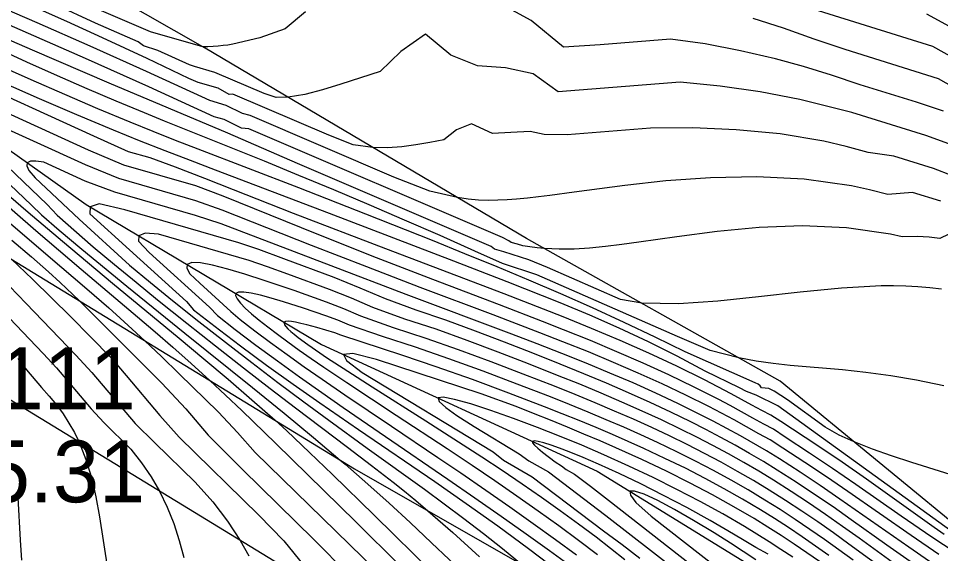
# Model space of a CAD drawing. Extents: x 2356077 to 2359823, y 225951 to 227822.
# Drawn here: x 2356810.76 to 2356847.97, y 227200.75 to 227222.36 of the extents above; entities that cross this region are included whole.
import ezdxf

# ---------------------------------------------------------------- set-up
doc = ezdxf.new("R2010")
doc.units = 0
for name, color, linetype in [('DTM Contours Major', 7, 'Continuous'), ('DTM Contours Minor', 7, 'Continuous'), ('Exist Roads EOP Cogo Elevation', 7, 'Continuous'), ('Exist Roads EOP Cogo Number', 7, 'Continuous'), ('PH Exist DTM Breakline', 7, 'Continuous')]:
    doc.layers.add(name, color=color, linetype=linetype)

msp = doc.modelspace()

# ---------------------------------------------------------------- linework, layer by layer
at = {"layer": 'DTM Contours Major'}
for points in [[(2356848.294, 227217.287), (2356847.369, 227217.623), (2356844.384, 227218.557), (2356842.283, 227219.085), (2356840.687, 227219.395), (2356839.073, 227219.622), (2356837.459, 227219.788), (2356832.543, 227219.386), (2356831.528, 227220.122), (2356830.407, 227220.355), (2356829.286, 227220.44), (2356828.21, 227220.876), (2356827.189, 227221.724), (2356826.195, 227221.017), (2356825.356, 227220.207), (2356823.771, 227219.702), (2356823.029, 227219.469), (2356822.318, 227219.283), (2356821.639, 227219.175), (2356821.162, 227219.162), (2356820.672, 227219.321), (2356818.687, 227220.172), (2356817.864, 227220.411), (2356817.666, 227220.483), (2356816.392, 227221.063), (2356815.81, 227221.256), (2356815.597, 227221.414), (2356813.867, 227222.16), (2356812.244, 227222.919)], [(2356848.104, 227207.527), (2356847.001, 227207.753), (2356845.953, 227207.929), (2356844.956, 227208.064), (2356844.004, 227208.166), (2356841.903, 227208.348), (2356841.218, 227208.424), (2356840.529, 227208.523), (2356839.83, 227208.656), (2356838.668, 227208.954), (2356837.346, 227209.514), (2356832.103, 227211.816), (2356831.671, 227212.001), (2356830.292, 227212.458), (2356829.182, 227212.961), (2356827.771, 227213.589), (2356826.345, 227214.213), (2356824.913, 227214.829), (2356823.486, 227215.433), (2356822.074, 227216.02), (2356820.688, 227216.587), (2356816.656, 227218.208), (2356815.848, 227218.54), (2356814.703, 227219.019), (2356813.535, 227219.518), (2356812.338, 227220.041), (2356811.106, 227220.589), (2356809.833, 227221.165)], [(2356847.899, 227200.71), (2356846.777, 227201.476), (2356844.221, 227203.26), (2356843.357, 227203.852), (2356842.486, 227204.431), (2356841.6, 227205.003), (2356841.095, 227205.337), (2356840.632, 227205.581), (2356840.137, 227205.866), (2356839.637, 227206.145), (2356839.13, 227206.418), (2356838.615, 227206.687), (2356837.69, 227207.148), (2356836.739, 227207.599), (2356835.764, 227208.038), (2356834.769, 227208.469), (2356833.755, 227208.89), (2356832.726, 227209.304), (2356831.799, 227209.667), (2356829.909, 227210.388), (2356826.966, 227211.498), (2356824.821, 227212.322), (2356822.59, 227213.194), (2356818.983, 227214.621), (2356817.924, 227214.995), (2356814.814, 227215.896), (2356813.462, 227216.44), (2356809.255, 227218.357)], [(2356809.031, 227217.596), (2356811.917, 227214.85), (2356812.332, 227214.413), (2356813.779, 227213.138), (2356814.638, 227212.422), (2356815.506, 227211.708), (2356816.375, 227211), (2356817.556, 227210.052), (2356818.714, 227209.135), (2356819.837, 227208.255), (2356820.915, 227207.421), (2356821.938, 227206.637), (2356824.036, 227205.052), (2356825.012, 227204.312), (2356825.885, 227203.632), (2356826.332, 227203.272), (2356826.794, 227202.891), (2356827.277, 227202.483), (2356828.283, 227201.603), (2356829.367, 227200.622)], [(2356810.496, 227213.404), (2356811.288, 227212.729), (2356811.972, 227212.127), (2356812.445, 227211.695), (2356812.953, 227211.216), (2356813.229, 227210.95), (2356813.932, 227210.26), (2356814.725, 227209.467), (2356816.544, 227207.632), (2356817.513, 227206.601), (2356818.412, 227205.536), (2356819.796, 227204.147), (2356822.685, 227201.325), (2356824.07, 227199.92)], [(2356844.445, 227200.48), (2356843.865, 227200.901), (2356843.281, 227201.317), (2356842.693, 227201.727), (2356842.097, 227202.131), (2356841.493, 227202.526), (2356840.876, 227202.914), (2356840.203, 227203.32), (2356839.512, 227203.716), (2356838.803, 227204.105), (2356838.073, 227204.486), (2356837.322, 227204.862), (2356836.548, 227205.234), (2356835.877, 227205.543), (2356835.187, 227205.85), (2356834.478, 227206.157), (2356833.748, 227206.463), (2356832.997, 227206.769), (2356832.224, 227207.077), (2356830.886, 227207.594), (2356829.51, 227208.11), (2356828.122, 227208.618), (2356826.779, 227209.078), (2356825.444, 227209.518), (2356824.126, 227209.971), (2356823.655, 227210.173), (2356823.169, 227210.354), (2356822.27, 227210.654), (2356821.46, 227210.912), (2356820.962, 227211.06), (2356820.522, 227211.179), (2356820.149, 227211.264), (2356819.854, 227211.308), (2356819.645, 227211.307), (2356819.532, 227211.256), (2356819.518, 227211.164), (2356819.582, 227211.031), (2356819.716, 227210.862), (2356819.914, 227210.66), (2356820.168, 227210.43), (2356820.472, 227210.175), (2356820.821, 227209.899), (2356821.208, 227209.605), (2356821.632, 227209.294), (2356822.087, 227208.968), (2356822.571, 227208.63), (2356823.079, 227208.281), (2356824.009, 227207.655), (2356825.997, 227206.345), (2356828.055, 227204.994), (2356829.072, 227204.317), (2356829.986, 227203.697), (2356830.873, 227203.084), (2356831.733, 227202.478), (2356832.564, 227201.88), (2356833.363, 227201.292), (2356834.128, 227200.714)], [(2356840.509, 227200.5), (2356839.484, 227201.173), (2356838.826, 227201.59), (2356837.997, 227202.093), (2356837.228, 227202.533), (2356836.553, 227202.89), (2356836.005, 227203.145), (2356835.619, 227203.277), (2356835.428, 227203.267), (2356835.454, 227203.105), (2356835.669, 227202.808), (2356836.287, 227202.263), (2356838.982, 227200.159)], [(2356810.742, 227203.013), (2356810.828, 227201.298), (2356810.891, 227200.486)]]:
    msp.add_lwpolyline(points, dxfattribs=at)
at = {"layer": 'DTM Contours Minor'}
for points in [[(2356822.339, 227222.622), (2356821.521, 227221.937), (2356820.498, 227221.571), (2356819.407, 227221.311), (2356819.214, 227221.282), (2356819.017, 227221.257), (2356818.817, 227221.237), (2356818.614, 227221.223), (2356818.408, 227221.215), (2356818.198, 227221.212), (2356816.089, 227221.821), (2356803.459, 227227.242)], [(2356847.981, 227214.974), (2356846.83, 227215.334), (2356845.84, 227215.251), (2356845.104, 227215.437), (2356844.372, 227215.596), (2356842.465, 227215.865), (2356840.553, 227215.962), (2356838.679, 227215.926), (2356836.887, 227215.798), (2356835.221, 227215.615), (2356833.189, 227215.344), (2356832.201, 227215.211), (2356831.74, 227215.154), (2356831.295, 227215.104), (2356830.862, 227215.063), (2356830.481, 227215.033), (2356830.101, 227215.015), (2356829.716, 227215.011), (2356829.321, 227215.025), (2356828.91, 227215.061), (2356828.478, 227215.122), (2356827.358, 227215.376), (2356825.912, 227215.953), (2356820.114, 227218.439), (2356819.805, 227218.52), (2356819.147, 227218.845), (2356818.491, 227219.037), (2356815.923, 227220.21), (2356813.658, 227221.23), (2356811.519, 227222.177), (2356807.094, 227224.108)], [(2356848, 227211.421), (2356847.53, 227211.48), (2356847.052, 227211.522), (2356846.565, 227211.548), (2356846.069, 227211.56), (2356845.563, 227211.556), (2356843.963, 227211.47), (2356842.304, 227211.305), (2356840.626, 227211.112), (2356838.973, 227210.941), (2356837.387, 227210.84), (2356835.91, 227210.859), (2356835.056, 227211.003), (2356832.104, 227212.298), (2356831.35, 227212.608), (2356830.349, 227212.937), (2356829.968, 227213.039), (2356829.835, 227213.15), (2356822.027, 227216.498), (2356819.205, 227217.719), (2356814.421, 227219.743), (2356811.327, 227221.073), (2356809.032, 227222.074), (2356806.487, 227223.197)], [(2356848.442, 227216.005), (2356847.683, 227216.296), (2356846.078, 227216.798), (2356845.051, 227216.939), (2356844.151, 227217.188), (2356843.251, 227217.398), (2356841.495, 227217.692), (2356839.723, 227217.862), (2356837.968, 227217.936), (2356836.26, 227217.927), (2356832.903, 227217.652), (2356831.97, 227217.671), (2356831.409, 227217.792), (2356830.626, 227217.755), (2356829.885, 227217.706), (2356829.041, 227218.101), (2356828.44, 227217.856), (2356827.922, 227217.456), (2356827.354, 227217.351), (2356826.79, 227217.253), (2356826.225, 227217.177), (2356825.65, 227217.137), (2356825.059, 227217.149), (2356824.261, 227217.254), (2356823.287, 227217.639), (2356819.419, 227219.297), (2356819.263, 227219.288), (2356818.826, 227219.535), (2356818.01, 227219.771), (2356817.638, 227219.934), (2356815.961, 227220.735), (2356814.152, 227221.579), (2356812.71, 227222.235), (2356811.174, 227222.923)], [(2356848.078, 227218.608), (2356846.992, 227218.969), (2356844.717, 227219.681), (2356843.565, 227220.061), (2356842.436, 227220.418), (2356841.307, 227220.727), (2356839.888, 227221.054), (2356838.465, 227221.332), (2356837.068, 227221.52), (2356834.232, 227221.288), (2356832.748, 227221.194), (2356831.45, 227222.272), (2356830.207, 227222.939)], [(2356850.161, 227219.827), (2356847.651, 227221.221), (2356842.002, 227222.988)], [(2356848.297, 227213.647), (2356847.932, 227213.471), (2356847.511, 227213.52), (2356847.027, 227213.553), (2356846.421, 227213.541), (2356845.944, 227213.648), (2356844.168, 227213.907), (2356842.396, 227213.981), (2356840.651, 227213.915), (2356838.954, 227213.753), (2356837.328, 227213.539), (2356835.794, 227213.319), (2356835.109, 227213.225), (2356834.447, 227213.145), (2356833.807, 227213.084), (2356833.185, 227213.046), (2356832.58, 227213.037), (2356831.991, 227213.063), (2356831.69, 227213.091), (2356831.392, 227213.129), (2356831.111, 227213.178), (2356830.902, 227213.239), (2356830.642, 227213.304), (2356830.545, 227213.374), (2356830.297, 227213.513), (2356820.053, 227217.905), (2356819.756, 227217.929), (2356819.069, 227218.27), (2356818.666, 227218.387), (2356816.023, 227219.593), (2356813.462, 227220.738), (2356809.076, 227222.665)], [(2356849.835, 227221.21), (2356847.411, 227222.524)], [(2356861.265, 227212.351), (2356847.885, 227219.916), (2356844.12, 227221.097), (2356842.862, 227221.521), (2356841.632, 227221.957), (2356840.407, 227222.359)], [(2356849.463, 227203.596), (2356846.804, 227204.426), (2356845.992, 227204.693), (2356845.218, 227204.969), (2356844.485, 227205.261), (2356843.868, 227205.538), (2356843.31, 227205.859), (2356841.792, 227206.955), (2356841.248, 227207.303), (2356841.032, 227207.409), (2356840.738, 227207.448), (2356840.689, 227207.522), (2356840.602, 227207.587), (2356840.491, 227207.651), (2356837.662, 227208.896), (2356836.449, 227209.492), (2356835.197, 227210.084), (2356833.923, 227210.667), (2356832.639, 227211.236), (2356831.361, 227211.784), (2356830.077, 227212.321), (2356828.776, 227212.855), (2356827.462, 227213.387), (2356824.78, 227214.456), (2356822.072, 227215.516), (2356818.012, 227217.08), (2356817.106, 227217.433), (2356816.194, 227217.795), (2356815.272, 227218.167), (2356813.964, 227218.711), (2356812.633, 227219.28), (2356811.281, 227219.872), (2356809.91, 227220.485)], [(2356806.008, 227219.847), (2356811.294, 227214.819), (2356811.689, 227214.429), (2356812.412, 227213.802), (2356813.316, 227213.047), (2356815.142, 227211.545), (2356817.473, 227209.655), (2356820.203, 227207.452), (2356821.478, 227206.416), (2356822.666, 227205.437), (2356823.748, 227204.524), (2356823.941, 227204.358), (2356824.854, 227203.559), (2356825.717, 227202.781), (2356826.564, 227202), (2356827.427, 227201.191), (2356829.568, 227199.161)], [(2356848.559, 227200.791), (2356847.608, 227201.42), (2356846.382, 227202.261), (2356844.541, 227203.545), (2356843.61, 227204.184), (2356842.673, 227204.81), (2356841.701, 227205.453), (2356841.232, 227205.78), (2356840.835, 227205.975), (2356840.392, 227206.216), (2356839.939, 227206.472), (2356839.481, 227206.724), (2356839.016, 227206.971), (2356838.026, 227207.475), (2356837.009, 227207.963), (2356835.969, 227208.438), (2356834.911, 227208.9), (2356833.838, 227209.349), (2356832.756, 227209.787), (2356831.9, 227210.124), (2356830.169, 227210.79), (2356827.487, 227211.81), (2356825.214, 227212.691), (2356822.818, 227213.64), (2356820.282, 227214.664), (2356819.016, 227215.18), (2356817.916, 227215.594), (2356815.009, 227216.437), (2356813.586, 227217.043), (2356807.483, 227219.823)], [(2356848.113, 227201.527), (2356847.714, 227201.805), (2356844.975, 227203.754), (2356843.991, 227204.44), (2356842.98, 227205.122), (2356841.519, 227206.08), (2356841.12, 227206.345), (2356840.753, 227206.526), (2356840.347, 227206.744), (2356839.937, 227206.974), (2356839.522, 227207.2), (2356838.437, 227207.767), (2356837.324, 227208.313), (2356836.191, 227208.84), (2356835.044, 227209.348), (2356833.889, 227209.838), (2356832.734, 227210.309), (2356831.942, 227210.624), (2356830.356, 227211.238), (2356825.588, 227213.051), (2356821.866, 227214.486), (2356819.434, 227215.433), (2356818.28, 227215.887), (2356817.103, 227216.355), (2356816.084, 227216.722), (2356815.208, 227216.976), (2356813.809, 227217.6), (2356808.368, 227220.079)], [(2356848.38, 227201.674), (2356841.402, 227206.714), (2356840.521, 227207.15), (2356840.135, 227207.29), (2356839.86, 227207.445), (2356838.466, 227208.121), (2356837.338, 227208.722), (2356836.181, 227209.296), (2356835.002, 227209.845), (2356833.811, 227210.37), (2356832.616, 227210.874), (2356831.907, 227211.163), (2356830.487, 227211.727), (2356828.323, 227212.563), (2356823.313, 227214.48), (2356818.715, 227216.227), (2356817.704, 227216.615), (2356816.683, 227217.012), (2356815.65, 227217.421), (2356814.604, 227217.845), (2356813.118, 227218.466), (2356811.617, 227219.111), (2356810.12, 227219.77)], [(2356807.744, 227217.036), (2356811.464, 227213.8), (2356813.296, 227212.232), (2356815.572, 227210.307), (2356816.277, 227209.704), (2356816.995, 227209.08), (2356817.731, 227208.427), (2356818.488, 227207.737), (2356819.12, 227207.147), (2356819.773, 227206.527), (2356821.154, 227205.191), (2356824.37, 227202.038), (2356826.17, 227200.259)], [(2356847.513, 227200.437), (2356846.68, 227201.009), (2356843.905, 227202.954), (2356843.104, 227203.502), (2356842.295, 227204.04), (2356841.471, 227204.574), (2356840.945, 227204.9), (2356839.889, 227205.502), (2356839.346, 227205.802), (2356838.794, 227206.096), (2356838.232, 227206.385), (2356837.366, 227206.811), (2356836.475, 227207.228), (2356835.561, 227207.638), (2356834.623, 227208.041), (2356833.665, 227208.439), (2356832.686, 227208.832), (2356831.685, 227209.223), (2356830.665, 227209.612), (2356826.412, 227211.206), (2356823.377, 227212.362), (2356818.944, 227214.059), (2356817.908, 227214.402), (2356814.655, 227215.345), (2356813.449, 227215.787), (2356811.781, 227216.547), (2356811.466, 227216.599), (2356811.244, 227216.595), (2356811.121, 227216.531), (2356811.103, 227216.404), (2356811.183, 227216.217), (2356811.443, 227215.925), (2356813.209, 227214.248), (2356815.25, 227212.396), (2356816.085, 227211.699), (2356816.982, 227210.973), (2356818.043, 227210.126), (2356819.11, 227209.288), (2356820.177, 227208.463), (2356821.233, 227207.658), (2356822.271, 227206.879), (2356823.283, 227206.132), (2356824.838, 227205.005), (2356827.144, 227203.346), (2356827.945, 227202.759), (2356828.737, 227202.167), (2356829.52, 227201.566), (2356830.294, 227200.951), (2356831.058, 227200.32)], [(2356808.814, 227215.457), (2356811.96, 227212.778), (2356813.524, 227211.438), (2356814.407, 227210.666), (2356814.869, 227210.254), (2356815.351, 227209.815), (2356815.859, 227209.343), (2356816.531, 227208.706), (2356817.25, 227208.011), (2356818.832, 227206.462), (2356819.596, 227205.642), (2356820.319, 227204.826), (2356825.205, 227200.053)], [(2356809.851, 227215.652), (2356811.155, 227214.533), (2356812.54, 227213.359), (2356814.559, 227211.672), (2356817.253, 227209.446), (2356818.248, 227208.618), (2356819.226, 227207.792), (2356820.183, 227206.964), (2356821.118, 227206.131), (2356821.586, 227205.702), (2356822.512, 227204.833), (2356823.44, 227203.94), (2356825.121, 227202.299), (2356829.932, 227197.561)], [(2356847.136, 227200.149), (2356845.795, 227201.096), (2356844.357, 227202.12), (2356843.626, 227202.632), (2356842.886, 227203.139), (2356842.137, 227203.637), (2356841.379, 227204.121), (2356840.82, 227204.463), (2356840.255, 227204.797), (2356839.681, 227205.124), (2356839.097, 227205.443), (2356838.502, 227205.758), (2356837.894, 227206.067), (2356837.082, 227206.463), (2356836.244, 227206.855), (2356835.38, 227207.242), (2356834.489, 227207.628), (2356833.57, 227208.013), (2356832.622, 227208.399), (2356831.516, 227208.838), (2356830.375, 227209.281), (2356829.201, 227209.731), (2356828, 227210.18), (2356826.811, 227210.572), (2356825.568, 227211.034), (2356824.553, 227211.469), (2356823.502, 227211.891), (2356821.474, 227212.652), (2356820.459, 227213.025), (2356819.658, 227213.298), (2356815.051, 227214.633), (2356814.017, 227214.871), (2356813.656, 227214.75), (2356813.643, 227214.473), (2356815.25, 227213.009), (2356817.548, 227210.922), (2356817.83, 227210.587), (2356818.877, 227209.786), (2356819.717, 227209.136), (2356820.777, 227208.36), (2356821.849, 227207.592), (2356822.921, 227206.838), (2356824.477, 227205.763), (2356827.556, 227203.655), (2356828.831, 227202.768), (2356830.098, 227201.866), (2356831.345, 227200.953), (2356832.559, 227200.029)], [(2356846.309, 227200.194), (2356844.679, 227201.369), (2356844.006, 227201.848), (2356843.326, 227202.324), (2356842.636, 227202.795), (2356841.937, 227203.258), (2356841.227, 227203.709), (2356840.631, 227204.073), (2356840.025, 227204.427), (2356839.408, 227204.774), (2356838.778, 227205.114), (2356838.135, 227205.448), (2356837.476, 227205.777), (2356836.71, 227206.144), (2356835.922, 227206.507), (2356835.11, 227206.868), (2356834.272, 227207.227), (2356833.408, 227207.586), (2356832.516, 227207.946), (2356831.338, 227208.41), (2356830.121, 227208.878), (2356828.872, 227209.35), (2356827.611, 227209.807), (2356826.357, 227210.22), (2356825.058, 227210.692), (2356824.204, 227211.058), (2356823.31, 227211.417), (2356821.634, 227212.032), (2356820.814, 227212.325), (2356820.067, 227212.582), (2356816.417, 227213.64), (2356815.88, 227213.687), (2356815.615, 227213.585), (2356815.604, 227213.37), (2356816.04, 227212.905), (2356818.47, 227210.699), (2356818.789, 227210.369), (2356819.501, 227209.804), (2356820.343, 227209.17), (2356821.213, 227208.529), (2356822.102, 227207.889), (2356823, 227207.253), (2356823.863, 227206.651), (2356825.576, 227205.473), (2356828.083, 227203.761), (2356829.178, 227203.005), (2356830.236, 227202.267), (2356831.245, 227201.554), (2356832.194, 227200.875), (2356833.072, 227200.236)], [(2356807.672, 227213.112), (2356811.208, 227209.407), (2356811.763, 227208.828), (2356812.297, 227208.254), (2356813.693, 227206.601), (2356814.207, 227206.037), (2356815.301, 227204.968), (2356815.734, 227204.409), (2356816.12, 227203.843), (2356816.458, 227203.267), (2356816.769, 227202.623), (2356817.028, 227201.963), (2356817.247, 227201.285), (2356817.435, 227200.591)], [(2356810.478, 227212.632), (2356811.327, 227211.828), (2356812.116, 227211.062), (2356812.867, 227210.316), (2356813.682, 227209.491), (2356814.488, 227208.665), (2356815.111, 227207.937), (2356816.472, 227206.326), (2356817.245, 227205.449), (2356820.462, 227202.306), (2356821.476, 227201.263), (2356822.271, 227200.27)], [(2356845.938, 227199.919), (2356844.27, 227201.134), (2356843.642, 227201.583), (2356843.008, 227202.027), (2356842.366, 227202.464), (2356841.715, 227202.892), (2356841.053, 227203.312), (2356840.419, 227203.696), (2356839.773, 227204.07), (2356839.112, 227204.437), (2356838.436, 227204.797), (2356837.742, 227205.151), (2356837.029, 227205.5), (2356836.311, 227205.838), (2356835.572, 227206.173), (2356834.811, 227206.506), (2356834.028, 227206.838), (2356833.219, 227207.171), (2356832.385, 227207.506), (2356831.132, 227207.995), (2356829.837, 227208.486), (2356828.517, 227208.978), (2356827.207, 227209.439), (2356825.901, 227209.869), (2356824.57, 227210.341), (2356823.895, 227210.63), (2356823.192, 227210.907), (2356821.892, 227211.367), (2356820.676, 227211.781), (2356819.902, 227212.03), (2356819.216, 227212.231), (2356818.594, 227212.394), (2356818.105, 227212.484), (2356817.758, 227212.497), (2356817.573, 227212.421), (2356817.56, 227212.27), (2356817.679, 227212.048), (2356818.079, 227211.667), (2356819.332, 227210.529), (2356819.709, 227210.202), (2356820.302, 227209.745), (2356820.936, 227209.272), (2356821.603, 227208.786), (2356822.297, 227208.292), (2356823.011, 227207.792), (2356823.931, 227207.16), (2356825.808, 227205.892), (2356827.687, 227204.631), (2356828.61, 227204.006), (2356829.616, 227203.315), (2356830.592, 227202.635), (2356831.531, 227201.97), (2356832.429, 227201.323), (2356833.28, 227200.699)], [(2356809.722, 227212.252), (2356811.079, 227210.846), (2356813.08, 227208.759), (2356813.727, 227208.068), (2356815.468, 227206.007), (2356816.264, 227205.218), (2356817.887, 227203.632), (2356818.6, 227202.844), (2356819.193, 227202.062), (2356819.707, 227201.283), (2356820.052, 227200.665)], [(2356843.459, 227200.669), (2356842.921, 227201.052), (2356842.378, 227201.428), (2356841.827, 227201.798), (2356841.267, 227202.161), (2356840.696, 227202.519), (2356839.976, 227202.949), (2356839.233, 227203.37), (2356838.464, 227203.784), (2356837.669, 227204.193), (2356836.846, 227204.596), (2356835.993, 227204.995), (2356835.368, 227205.277), (2356834.726, 227205.558), (2356834.068, 227205.838), (2356833.391, 227206.118), (2356832.697, 227206.398), (2356831.985, 227206.68), (2356830.544, 227207.231), (2356829.075, 227207.774), (2356827.621, 227208.294), (2356826.265, 227208.746), (2356823.768, 227209.568), (2356823.522, 227209.66), (2356822.8, 227209.875), (2356822.395, 227209.986), (2356822.154, 227210.045), (2356821.946, 227210.089), (2356821.774, 227210.117), (2356821.639, 227210.128), (2356821.544, 227210.119), (2356821.49, 227210.091), (2356821.479, 227210.048), (2356821.5, 227209.989), (2356821.553, 227209.914), (2356821.636, 227209.825), (2356821.747, 227209.722), (2356821.885, 227209.607), (2356822.048, 227209.479), (2356822.444, 227209.188), (2356822.925, 227208.854), (2356823.195, 227208.673), (2356824.056, 227208.109), (2356825.031, 227207.486), (2356827.199, 227206.113), (2356828.332, 227205.39), (2356829.456, 227204.66), (2356830.282, 227204.112), (2356831.085, 227203.568), (2356831.865, 227203.028), (2356832.622, 227202.49), (2356833.356, 227201.956), (2356834.065, 227201.424), (2356834.654, 227200.971), (2356835.229, 227200.518)], [(2356810.733, 227208.624), (2356811.091, 227208.175), (2356811.698, 227207.457), (2356812.007, 227207.107), (2356812.297, 227206.757), (2356812.562, 227206.387), (2356812.802, 227206.014), (2356813.018, 227205.636), (2356813.209, 227205.251), (2356813.487, 227204.552), (2356813.707, 227203.817), (2356813.882, 227203.044), (2356814.029, 227202.236), (2356814.353, 227200.143)], [(2356843.077, 227200.434), (2356842.572, 227200.787), (2356842.06, 227201.137), (2356841.537, 227201.482), (2356841, 227201.824), (2356840.448, 227202.164), (2356839.627, 227202.644), (2356838.765, 227203.121), (2356837.86, 227203.597), (2356836.909, 227204.072), (2356835.909, 227204.547), (2356834.858, 227205.024), (2356834.226, 227205.301), (2356833.576, 227205.578), (2356832.912, 227205.856), (2356832.233, 227206.133), (2356831.542, 227206.408), (2356830.839, 227206.683), (2356829.431, 227207.203), (2356825.21, 227208.592), (2356824.253, 227208.824), (2356823.88, 227208.789), (2356823.998, 227208.544), (2356824.635, 227208.062), (2356829.916, 227204.856), (2356830.339, 227204.518), (2356831.485, 227203.853), (2356834.367, 227201.676), (2356835.116, 227201.12), (2356835.835, 227200.57)], [(2356842, 227200.602), (2356841.526, 227200.918), (2356841.045, 227201.229), (2356840.556, 227201.537), (2356840.055, 227201.841), (2356839.178, 227202.351), (2356838.269, 227202.852), (2356837.332, 227203.342), (2356836.369, 227203.82), (2356835.386, 227204.286), (2356834.384, 227204.737), (2356833.492, 227205.122), (2356832.597, 227205.491), (2356831.709, 227205.842), (2356830.73, 227206.21), (2356829.815, 227206.533), (2356829.009, 227206.795), (2356828.356, 227206.977), (2356827.902, 227207.062), (2356827.69, 227207.034), (2356827.74, 227206.894), (2356828.005, 227206.653), (2356828.449, 227206.328), (2356829.15, 227205.879), (2356830.965, 227204.777), (2356831.355, 227204.5), (2356832.149, 227204.049), (2356834.464, 227202.295), (2356838.306, 227199.297)], [(2356841.005, 227200.729), (2356840.509, 227201.001), (2356840.039, 227201.277), (2356839.606, 227201.54), (2356838.672, 227202.084), (2356837.73, 227202.607), (2356836.794, 227203.102), (2356835.879, 227203.563), (2356834.999, 227203.985), (2356834.171, 227204.362), (2356833.548, 227204.631), (2356832.978, 227204.862), (2356832.592, 227205.01), (2356832.25, 227205.13), (2356831.961, 227205.22), (2356831.735, 227205.278), (2356831.578, 227205.298), (2356831.501, 227205.279), (2356831.505, 227205.222), (2356831.579, 227205.13), (2356831.714, 227205.005), (2356831.905, 227204.849), (2356832.422, 227204.456), (2356832.669, 227204.293), (2356832.861, 227204.146), (2356833.192, 227203.958), (2356833.839, 227203.468), (2356834.565, 227202.912), (2356838.756, 227199.641)]]:
    msp.add_lwpolyline(points, dxfattribs=at)
at = {"layer": 'PH Exist DTM Breakline'}
for points in [[(2356855.847, 227178.772), (2356834.49, 227192.255), (2356810.399, 227206.967), (2356788.735, 227220.136), (2356766.278, 227233.766), (2356744.171, 227246.698), (2356720.307, 227261.266), (2356695.176, 227276.508), (2356674.936, 227288.289), (2356652.397, 227302.228), (2356630.481, 227315.802), (2356612.536, 227326.207), (2356593.177, 227338.498), (2356576.924, 227348.664), (2356557.519, 227360.393), (2356536.799, 227373.48)], [(2356598.346, 227344.988), (2356610.985, 227337.882), (2356624.757, 227330.619), (2356633.489, 227324.349), (2356646.025, 227317.874), (2356660.346, 227309.675), (2356674.025, 227301.367), (2356685.554, 227293.579), (2356704.848, 227281.062), (2356719.296, 227272.924), (2356732.757, 227265.163), (2356747.196, 227256.79), (2356757.161, 227250.113), (2356766.932, 227244.619), (2356779.34, 227236.291), (2356790.423, 227229.967), (2356803.979, 227221.604), (2356813.49, 227214.849), (2356822.994, 227209.197), (2356834.106, 227204.079), (2356840.653, 227200.058), (2356845.766, 227194.655), (2356853.969, 227189.123)], [(2356849.479, 227201.151), (2356841.501, 227207.716), (2356831.266, 227213.47), (2356818.296, 227221.156), (2356803.747, 227229.459), (2356792.725, 227238.092), (2356780.814, 227244.788), (2356767.706, 227252.157), (2356757.219, 227258.47), (2356745.167, 227265.849), (2356732.916, 227272.736), (2356723.277, 227279.91)], [(2356701.726, 227278.246), (2356715.471, 227270.812), (2356729.359, 227262.131), (2356738.661, 227255.665), (2356750.12, 227250.753), (2356761.713, 227243.85), (2356773.041, 227235.362), (2356785.512, 227228.645), (2356797.791, 227220.404), (2356811.601, 227211.944), (2356824.322, 227204.174), (2356835.217, 227197.94), (2356847.087, 227190.239), (2356863.916, 227179.1)]]:
    msp.add_lwpolyline(points, dxfattribs=at)

# ---------------------------------------------------------------- texts
at = {"layer": 'Exist Roads EOP Cogo Elevation'}
msp.add_text('15.31', height=2.5, dxfattribs=at).set_placement((2356807.508, 227202.821))
at = {"layer": 'Exist Roads EOP Cogo Number'}
msp.add_text('D111', height=2.5, dxfattribs=at).set_placement((2356807.508, 227206.571))

doc.saveas('drawing.dxf')
